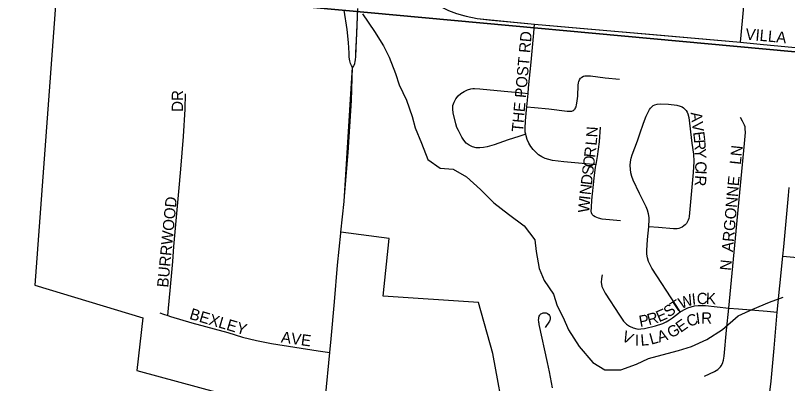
# Model space of a CAD drawing. Extents: x 1410790 to 1770854, y 566777 to 831614.
# Drawn here: x 1601925 to 1605354, y 717677 to 719313 of the extents above; entities that cross this region are included whole.
import ezdxf

# ---------------------------------------------------------------- set-up
doc = ezdxf.new("R2010")
doc.units = 0
for name, color, linetype in [('GM_X_City_Street', 7, 'Continuous'), ('GM_X_City_Street_Text', 7, 'Continuous'), ('GM_X_Corporation', 7, 'Continuous'), ('GM_X_County_Road', 7, 'Continuous'), ('GM_X_Minor_River', 7, 'Continuous'), ('GM_X_Section', 7, 'Continuous'), ('GM_X_State_Route', 7, 'Continuous'), ('GM_X_Township_Subdivision', 7, 'Continuous'), ('GM_X_Township_Subdivision_Text', 7, 'Continuous')]:
    doc.layers.add(name, color=color, linetype=linetype)

msp = doc.modelspace()

# ---------------------------------------------------------------- linework, layer by layer
at = {"layer": 'GM_X_City_Street'}
for points in [[(1604201.6, 718966.7), (1604203.9, 718991.4), (1604214.5, 719105.6), (1604226.5, 719236.3), (1604230.1, 719275.1)], [(1605158, 719193.1), (1605246.3, 719184.6), (1605420, 719167.9)], [(1604196.2, 718907.4), (1604229.4, 718904.5), (1604294.1, 718898.9), (1604374.5, 718888.4), (1604390.7, 718887.7), (1604395.4, 718888.5), (1604398.8, 718889.6), (1604402.6, 718891.6), (1604405.3, 718894), (1604407.8, 718896.4), (1604410, 718899.1), (1604411.9, 718902.5), (1604414.2, 718907.4), (1604416.8, 718915.7), (1604418.5, 718923), (1604422.2, 718955.2), (1604424.3, 719003.9), (1604425.6, 719013.7), (1604426.9, 719020.1), (1604430.4, 719028), (1604434.3, 719034.2), (1604436.9, 719036.8), (1604439.9, 719038.9), (1604446.8, 719042.9), (1604453.6, 719044.4), (1604462.4, 719045.6), (1604478.8, 719044.4), (1604543.5, 719036.5), (1604608, 719030.9)], [(1604190.8, 718786.1), (1604160.1, 718775.9), (1604113.2, 718760.4), (1604051.3, 718737.9), (1604019.6, 718729.1), (1604003.4, 718726.3), (1603986.9, 718725.1), (1603970.5, 718725.6), (1603954.5, 718729.5), (1603939.6, 718736.5), (1603926.4, 718746.3), (1603916.1, 718759.1), (1603907.1, 718773), (1603891.8, 718801.8), (1603885.6, 718816.2), (1603880.3, 718832), (1603868.8, 718880.1), (1603866.5, 718896.4), (1603867.4, 718912.8), (1603872.3, 718928.5), (1603880.5, 718942.8), (1603890.9, 718955.5), (1603903.3, 718966.2), (1603917.2, 718975), (1603931.9, 718982.5), (1603947.4, 718987.7), (1603955.7, 718989.5), (1603963.7, 718989.3), (1603986.8, 718987.5), (1604095.1, 718977), (1604177.1, 718969.1), (1604201.6, 718966.7)], [(1604196.2, 718907.4), (1604201.6, 718966.7)], [(1604190.8, 718786.1), (1604189.1, 718794.4), (1604188, 718811.4), (1604190, 718844.7), (1604194.9, 718893.5), (1604196.2, 718907.4)], [(1604737.1, 718374.2), (1604737.9, 718382.4), (1604738.7, 718398.9), (1604738.5, 718415.4), (1604736.3, 718431.7), (1604731.8, 718447.6), (1604725.6, 718462.9), (1604696.5, 718522.3), (1604668, 718581.9), (1604662.3, 718597.3), (1604658.2, 718613.4), (1604655.7, 718629.7), (1604654.9, 718646.2), (1604655.9, 718662.7), (1604658.9, 718678.9), (1604663.7, 718694.7), (1604687, 718756.5), (1604698.2, 718787.5), (1604714.2, 718834.9), (1604726, 718865.8), (1604732.6, 718880.9), (1604740.4, 718895.4), (1604745.6, 718901.7), (1604750.8, 718907.8), (1604756.6, 718912.5), (1604764.4, 718916.9), (1604774.5, 718919.8), (1604791.3, 718920.9)], [(1604791.3, 718920.9), (1604824.3, 718918.5), (1604861.7, 718914.8), (1604877.5, 718910.5), (1604885, 718906.8), (1604891.7, 718902.6), (1604897.9, 718896.5), (1604903.1, 718890.9), (1604907.3, 718883.8), (1604910.7, 718876.4), (1604914.7, 718860.5), (1604928.9, 718746.3), (1604935.7, 718697.5), (1604937.4, 718664.8), (1604934.8, 718615.6), (1604927.3, 718533.8), (1604920.5, 718468.5), (1604916.6, 718419.3), (1604914.9, 718410.9), (1604912.5, 718403.6), (1604908.3, 718395.3), (1604904.4, 718389.4), (1604898.4, 718382.9), (1604892.8, 718377.8), (1604885.2, 718372.4), (1604878.6, 718369.8), (1604870.4, 718366.9), (1604862.8, 718365.6), (1604846.5, 718364.7), (1604781, 718370.4), (1604737.1, 718374.2)], [(1605092.3, 718013.3), (1605163.1, 718744.4), (1605166.3, 718793.3), (1605165.9, 718809.6), (1605164.9, 718817.7), (1605162.7, 718825.7), (1605154.3, 718843.6), (1605144.7, 718859.5)], [(1604503.5, 718650.3), (1604510.1, 718686.7), (1604518.5, 718751.3), (1604522.9, 718816.4)], [(1604503.5, 718650.3), (1604489.9, 718651.5), (1604359.5, 718663.4), (1604310.4, 718669.4), (1604293.9, 718672.7), (1604277.7, 718677.9), (1604262.3, 718685.2), (1604248.1, 718694.6), (1604235.2, 718705.7), (1604223.6, 718718.1), (1604213.4, 718731.7), (1604204.7, 718746.2), (1604197.6, 718761.6), (1604192.4, 718777.7), (1604190.8, 718786.1)], [(1604611.2, 718400.3), (1604562.4, 718404.8), (1604530.1, 718408.7), (1604514.2, 718412.4), (1604499, 718418.3), (1604491.6, 718422.9), (1604486.5, 718428.5), (1604483, 718436.2), (1604482.1, 718443.8), (1604482.3, 718460.2), (1604485.1, 718492.7), (1604494.8, 718590.1), (1604501.3, 718638.5), (1604503.5, 718650.3)], [(1605332.5, 718244.3), (1605336.8, 718285.8), (1605357.8, 718512.7), (1605361.3, 718548.6)], [(1604877.4, 717995.9), (1604859.1, 718024.1), (1604751.1, 718190.3), (1604743.1, 718204.7), (1604736.6, 718219.9), (1604731.8, 718235.7), (1604729.1, 718251.9), (1604728.3, 718268.4), (1604731.5, 718317.9), (1604737.1, 718374.2)], [(1605308.3, 717994.9), (1605318.8, 718111.5), (1605332.5, 718244.3)], [(1605332.5, 718244.3), (1605381.4, 718239.8), (1605577.6, 718221.5), (1605659.1, 718210.2), (1605700.3, 718201.5)], [(1604529.8, 718160.4), (1604527.4, 718143.8), (1604526.4, 718126.6), (1604526.9, 718119.3), (1604529.2, 718109.4), (1604535.6, 718093.6), (1604543.6, 718079), (1604606.8, 717982), (1604625.8, 717954.3), (1604637.8, 717941.9), (1604652, 717932), (1604667.7, 717924.6), (1604684.8, 717920.6), (1604693.5, 717919.9), (1604702.1, 717920.3), (1604719, 717922.7), (1604767.4, 717934.7), (1604799.1, 717945), (1604814.6, 717951.7), (1604829.3, 717960), (1604843.1, 717969.6), (1604869, 717990), (1604877.4, 717995.9)], [(1604877.4, 717995.9), (1604882.1, 717999.1), (1604896, 718007.1), (1604910.6, 718013.8), (1604925.7, 718019.1), (1604941, 718022.7), (1604956.8, 718024.6), (1604972.9, 718024.8), (1604989.1, 718024), (1605092.3, 718013.3)], [(1604309.8, 717658.4), (1604296.3, 717729.1), (1604287.6, 717771.5), (1604250.7, 717940.2), (1604249.9, 717944.4), (1604249.3, 717948.2), (1604248.6, 717952.6), (1604248.3, 717959.8), (1604248.8, 717967.3), (1604249.7, 717972.6), (1604250.7, 717976.4), (1604253, 717981.2), (1604255.5, 717984.5), (1604258.5, 717987.2), (1604261.9, 717989.5), (1604264.7, 717990.7), (1604268.8, 717991.7), (1604271.7, 717992.1), (1604276.2, 717992.1), (1604279, 717991.7), (1604282, 717991.1), (1604285.2, 717989.9), (1604288, 717988.6), (1604293, 717984.9), (1604296.7, 717980.6), (1604298.2, 717977.5), (1604299.2, 717974.4), (1604299.9, 717969.6), (1604299.8, 717966.1), (1604299.1, 717962.3), (1604298, 717958.8), (1604296.1, 717954.9), (1604277.6, 717926.6)], [(1604984.6, 717710.3), (1605029.8, 717731.8), (1605044.2, 717740.2), (1605050.7, 717745.7), (1605056.1, 717751.7), (1605059.3, 717756.7), (1605064.3, 717766.2), (1605069, 717782.2), (1605071.6, 717798.7), (1605082.7, 717915.2), (1605092.3, 718013.3)], [(1605092.3, 718013.3), (1605135.4, 718009.6), (1605263.6, 717998.7), (1605308.3, 717994.9)], [(1605115.9, 717208.9), (1605131.6, 717229.7), (1605158.4, 717270.6), (1605199.4, 717341.4), (1605220.8, 717385.3), (1605233.3, 717415.4), (1605248.5, 717461.7), (1605256.1, 717493.2), (1605263.4, 717541.4), (1605280.4, 717687.9), (1605293.9, 717834.7), (1605308.3, 717994.9)]]:
    msp.add_lwpolyline(points, dxfattribs=at)
at = {"layer": 'GM_X_Corporation'}
for points in [[(1603883.7, 719321.5), (1603925.9, 719310.6), (1603975.4, 719300.1), (1604230.1, 719275.1), (1605144.6, 719194.4), (1605148.2, 719226.1), (1605218.5, 719998.8)], [(1602109.1, 719460.5), (1602011, 718114.3), (1602490.2, 717970.2), (1602464.2, 717735.8), (1602828.7, 717636.9)], [(1604102, 717497.7), (1604044.5, 717810.4), (1603980.6, 718038.4), (1603557.9, 718065.7), (1603584.4, 718321.5), (1603369.8, 718350.9), (1603384.2, 718486.1), (1603421.6, 719083.1), (1603425.9, 719087), (1603427.9, 719090), (1603429.5, 719092.7), (1603432.5, 719100), (1603434, 719108.2), (1603435.1, 719116.6), (1603435.9, 719130.8), (1603445, 719343.6)]]:
    msp.add_lwpolyline(points, dxfattribs=at)
at = {"layer": 'GM_X_County_Road'}
for points in [[(1603661.2, 719482.9), (1603677.3, 719463.3), (1603699.9, 719439), (1603724.1, 719416.1), (1603749.6, 719394.9), (1603776.6, 719375.4), (1603805, 719358.1), (1603824.4, 719347), (1603848.3, 719335), (1603883.7, 719321.5), (1603914, 719313.9), (1603925.9, 719310.5), (1603975.4, 719300.1), (1604040, 719292.4), (1604121.6, 719284.6), (1604230.1, 719275.1)], [(1604230.1, 719275.1), (1604431.7, 719257.4), (1604757.7, 719228.3), (1605144.2, 719194.4), (1605144.7, 719194.4), (1605158, 719193.1)]]:
    msp.add_lwpolyline(points, dxfattribs=at)
at = {"layer": 'GM_X_Minor_River'}
for points in [[(1603466, 719320.7), (1603519.3, 719242.2), (1603558.8, 719177.8), (1603584.4, 719127.5), (1603611.8, 719055.3), (1603629.4, 719005.1), (1603660.9, 718936.8), (1603686.3, 718864.5), (1603699.9, 718814.3), (1603727.3, 718746.1), (1603756.8, 718673.8), (1603810.4, 718635.3), (1603868.3, 718630.9), (1603928, 718596.4), (1603989.5, 718539.8), (1604048.9, 718481.3), (1604114.5, 718430.8), (1604184, 718378.2), (1604231.5, 718315.8), (1604237.1, 718263.7), (1604250.5, 718189.5), (1604272.1, 718135.3), (1604313.5, 718074.9), (1604331.1, 718022.7), (1604356.7, 717970.5), (1604380.3, 717916.2), (1604427.6, 717841.8)], [(1604427.6, 717841.8), (1604489, 717771.2), (1604542.7, 717738.8), (1604612.6, 717738.3), (1604682.7, 717763.8), (1604736.8, 717789.4), (1604796.9, 717804.9), (1604868.9, 717824.4), (1604927, 717842), (1604995.2, 717873.5), (1605065.4, 717917.1), (1605133.8, 717978.6), (1605199.9, 718008.1), (1605274, 718039.6), (1605334.1, 718061.2)]]:
    msp.add_lwpolyline(points, dxfattribs=at)
at = {"layer": 'GM_X_Section'}
for points in [[(1600850, 724846), (1606124.7, 724419.8), (1605628.3, 719130), (1600348.4, 719616.3), (1600834, 724846.2)], [(1600348.4, 719616.3), (1605628.3, 719130), (1605148.2, 713864), (1599854.3, 714342.5)]]:
    msp.add_lwpolyline(points, close=True, dxfattribs=at)
at = {"layer": 'GM_X_State_Route'}
for points in [[(1603421.6, 719083.1), (1603417, 719090.6), (1603412.6, 719099.3), (1603409.1, 719112.3), (1603407.1, 719128.5), (1603406.2, 719145.7), (1603403.7, 719193.4), (1603397.3, 719251.5), (1603384, 719337)], [(1603421.6, 719083.1), (1603425.9, 719087), (1603428, 719090), (1603429.5, 719092.7), (1603432.5, 719100), (1603434, 719108.2), (1603435.1, 719116.6), (1603435.9, 719130.7), (1603436.3, 719147.5), (1603440.2, 719231.6), (1603445, 719343.6)], [(1603271.4, 717290.1), (1603271.6, 717292.4), (1603301.8, 717617), (1603320.3, 717815.3), (1603326.1, 717876.5), (1603340.9, 718040.6), (1603355.6, 718203.8), (1603369.3, 718345.9), (1603369.8, 718350.9), (1603384.2, 718486.1), (1603384.7, 718490.7), (1603402.3, 718704.8), (1603416.5, 718935.6), (1603421.6, 719083.1)]]:
    msp.add_lwpolyline(points, dxfattribs=at)
at = {"layer": 'GM_X_Township_Subdivision'}
for points in [[(1602601.9, 717979.3), (1602604.9, 718012.2), (1602607.7, 718044.3), (1602612.9, 718107.5), (1602618.5, 718171.4), (1602623.1, 718220.4), (1602628.3, 718285.9), (1602650.6, 718531.7), (1602659.1, 718630.6), (1602671.5, 718774.8), (1602677.7, 718896.4), (1602679.5, 718964.7)], [(1602566, 717991.2), (1602581.5, 717986), (1602601.9, 717979.3)], [(1602601.9, 717979.3), (1602612.8, 717975.8), (1602707.7, 717946.7), (1602868.1, 717903.8), (1602932.7, 717883.9), (1602994.4, 717869), (1603061.1, 717856.2), (1603268.8, 717823.5), (1603320.3, 717815.3)]]:
    msp.add_lwpolyline(points, dxfattribs=at)

# ---------------------------------------------------------------- texts
at = {"layer": 'GM_X_City_Street_Text'}
for s, rotation, p in [('VILLA', 354.5626, (1605165, 719206.9)), ('THE POST RD', 84.8024, (1604177.9, 718793.5)), ('A', 277.2985, (1604922.6, 718881.9)), ('V', 277.2985, (1604928.2, 718838.3)), ('N', 86.6715, (1604508.7, 718770.5)), ('L', 84.7966, (1604505.4, 718733.6)), ('E', 277.2029, (1604933.8, 718794.7)), ('R', 274.205, (1604938.2, 718760.4)), ('R', 83.2093, (1604499, 718679.7)), ('Y', 272.0329, (1604941, 718721.4)), ('LN', 83.9946, (1605146, 718648.5)), ('O', 83.2301, (1604493.8, 718636)), ('S', 83.2305, (1604489.7, 718601)), ('C', 271.457, (1604943, 718664.4)), ('D', 83.2084, (1604484.5, 718557.3)), ('R', 266.8417, (1604943.7, 718603.9)), ('I', 268.9949, (1604944, 718625.4)), ('ARGONNE', 84.8718, (1605110.7, 718261.2)), ('N', 83.2084, (1604479.2, 718513.6)), ('W', 85.8437, (1604472.7, 718435.3)), ('I', 83.5149, (1604476.8, 718491.9)), ('N', 84.2916, (1605102, 718177.6)), ('T', 33.584, (1604853.7, 717989.8)), ('W', 20.4931, (1604880.3, 718007.9)), ('I', 6.0456, (1604930.7, 718027.2)), ('C', 2.843, (1604951.8, 718029.5)), ('K', 358.2292, (1604990.3, 718031.4)), ('S', 36.0378, (1604825.7, 717969.4)), ('P', 10.6616, (1604698.6, 717928.9)), ('R', 15.4159, (1604737.6, 717936.5)), ('E', 23.4022, (1604782.9, 717949.5)), ('C', 20.3172, (1604915.7, 717928.4)), ('I', 7.6726, (1604950, 717941.5)), ('R', 359.1257, (1604969.8, 717944.3)), ('E', 35.4754, (1604879.2, 717902.1)), ('V', 334.1974, (1604612.8, 717870.1)), ('A', 16.889, (1604783.1, 717859.7)), ('G', 29.7983, (1604836.4, 717877.3)), ('I', 359.7098, (1604675.9, 717845.5)), ('L', 4.1934, (1604702.2, 717845.5)), ('L', 15.487, (1604747.9, 717849.9))]:
    msp.add_text(s, height=50, rotation=rotation, dxfattribs=at).set_placement(p)
at = {"layer": 'GM_X_Township_Subdivision_Text'}
for s, rotation, p in [('DR', 90, (1602668.7, 718885.1)), ('BURRWOOD', 84.4298, (1602602.7, 718102.8)), ('BEXLEY', 343.4932, (1602694.1, 717965.7)), ('AVE', 352.1508, (1603101.8, 717860.4))]:
    msp.add_text(s, height=50, rotation=rotation, dxfattribs=at).set_placement(p)

doc.saveas('drawing.dxf')
